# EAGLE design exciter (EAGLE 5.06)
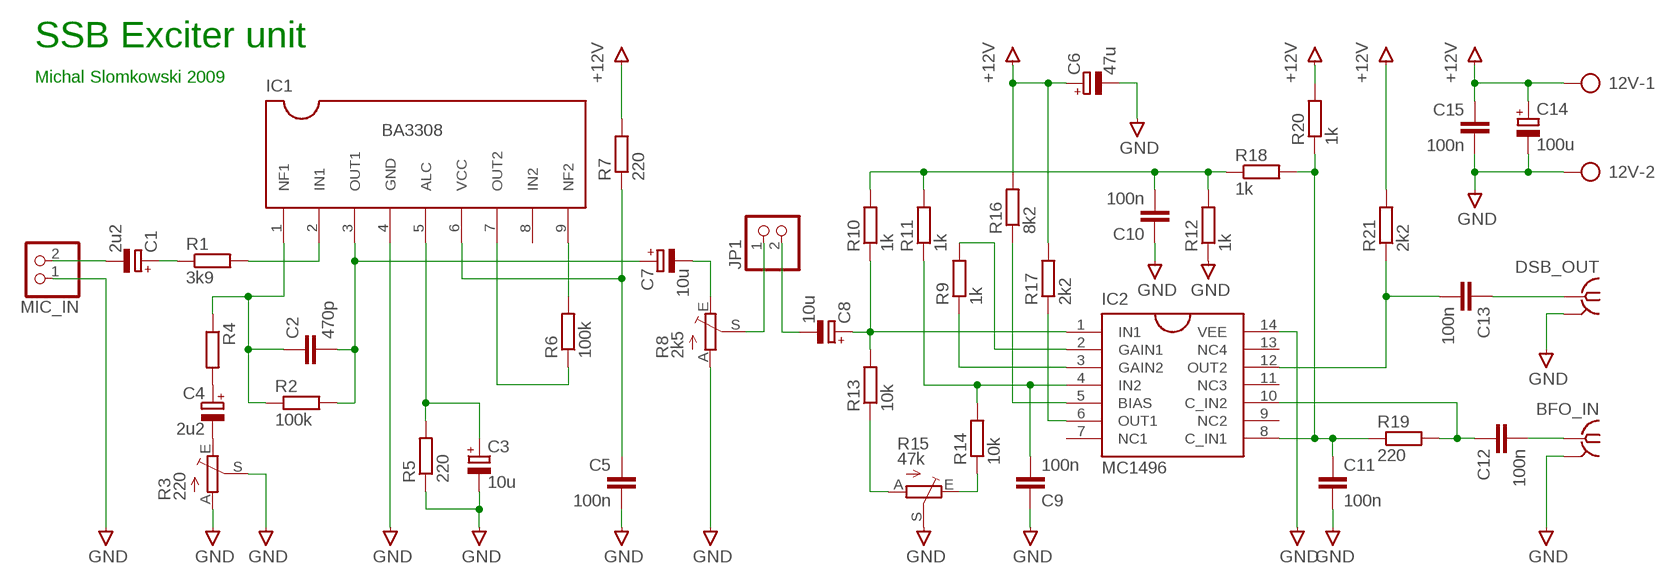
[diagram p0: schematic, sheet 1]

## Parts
12V  AK500/2  [AK500/2]
BFO_IN  BU-SMB-V  [BU-SMB-V]
C1  2u2  CPOL-EUE2.5-7  [E2,5-7]
C2  470p  C-EUC1206  [C1206]
C3  10u  CPOL-EUE2.5-7  [E2,5-7]
C4  2u2  CPOL-EUE2.5-7  [E2,5-7]
C5  100n  C-EUC1206  [C1206]
C6  47u  CPOL-EUE2.5-7  [E2,5-7]
C7  10u  CPOL-EUE2.5-7  [E2,5-7]
C8  10u  CPOL-EUE2.5-7  [E2,5-7]
C9  100n  C-EUC1206  [C1206]
C10  100n  C-EUC1206  [C1206]
C11  100n  C-EUC1206  [C1206]
C12  100n  C-EUC1206  [C1206]
C13  100n  C-EUC1206  [C1206]
C14  100u  CPOL-EUE2.5-7  [E2,5-7]
C15  100n  C-EUC1206  [C1206]
DSB_OUT  BU-SMB-V  [BU-SMB-V]
IC1  BA3308  [SIP9]
IC2  MC1496  [DIL14]
JP1  PINHD-1X2  [1X02]
MIC_IN  PINHD-1X2  [1X02]
R1  3k9  R-EU_R1206  [R1206]
R2  100k  R-EU_R1206  [R1206]
R3  220  TRIM_EU-ECP10S  [ECP10S]
R4  R-EU_R1206  [R1206]
R5  220  R-EU_R1206  [R1206]
R6  100k  R-EU_R1206  [R1206]
R7  220  R-EU_R1206  [R1206]
R8  2k5  TRIM_EU-ECP10S  [ECP10S]
R9  1k  R-EU_R1206  [R1206]
R10  1k  R-EU_R1206  [R1206]
R11  1k  R-EU_R1206  [R1206]
R12  1k  R-EU_R1206  [R1206]
R13  10k  R-EU_R1206  [R1206]
R14  10k  R-EU_R1206  [R1206]
R15  47k  TRIM_EU-S64W  [S64W]
R16  8k2  R-EU_R1206  [R1206]
R17  2k2  R-EU_R1206  [R1206]
R18  1k  R-EU_R1206  [R1206]
R19  220  R-EU_R1206  [R1206]
R20  1k  R-EU_R1206  [R1206]
R21  2k2  R-EU_R1206  [R1206]

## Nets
GND: 12V.2 BFO_IN.2(GND) C3.- C5.2 C6.- C9.1 C10.1 C11.2 C14.- C15.2 DSB_OUT.2(GND) IC1.4(GND) IC2.14(VEE) MIC_IN.1 R3.A R3.S R5.1 R8.A R12.1 R15.S
N$1: C1.- MIC_IN.2
N$2: C1.+ R1.1
N$3: IC1.2(IN1) R1.2
N$4: C2.2 C7.+ IC1.3(OUT1) R2.2
N$5: C3.+ IC1.5(ALC) R5.2
N$6: C2.1 IC1.1(NF1) R2.1 R4.1
N$7: C4.+ R4.2
N$8: C4.- R3.E
N$9: IC1.9(NF2) R6.2
N$10: IC1.7(OUT2) R6.1
N$11: C5.1 IC1.6(VCC) R7.1
N$12: C7.- R8.E
N$13: C8.- JP1.2
N$15: IC2.3(GAIN2) R9.1
N$16: IC2.2(GAIN1) R9.2
N$17: C9.2 IC2.4(IN2) R11.1 R14.2
N$18: C10.2 R10.2 R11.2 R12.2 R18.1
N$19: R14.1 R15.E
N$20: R13.1 R15.A
N$21: IC2.5(BIAS) R16.1
N$22: IC2.6(OUT1) R17.1
N$23: C12.1 IC2.10(C_IN2) R19.2
N$25: BFO_IN.1 C12.2
N$26: C13.2 IC2.12(OUT2) R21.1
N$27: C13.1 DSB_OUT.1
N$28: JP1.1 R8.S
N$38: C11.1 IC2.8(C_IN1) R18.2 R19.1 R20.1
N$54: C8.+ IC2.1(IN1) R10.1 R13.2
N$78: 12V.1 C6.+ C14.+ C15.1 R7.2 R16.2 R17.2 R20.2 R21.2 ; supply symbol labelled +12V
Unconnected: IC1.8(IN2) IC2.7(NC1) IC2.9(NC2) IC2.11(NC3) IC2.13(NC4)

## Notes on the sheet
- SSB Exciter unit
- Michal Slomkowski 2009

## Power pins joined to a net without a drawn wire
GND: BFO_IN.3(GND) BFO_IN.4(GND) BFO_IN.5(GND) DSB_OUT.3(GND) DSB_OUT.4(GND) DSB_OUT.5(GND)

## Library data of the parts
12V = con-ptr500:AK500/2: CONNECTOR
BFO_IN DSB_OUT = con-coax:BU-SMB-V: FEMALE SMB CONNECTOR Radiall distributor RS 112-2993
C1 C3 C4 C6-C8 C14 = rcl:CPOL-EU: POLARIZED CAPACITOR, European symbol
C2 C5 C9-C13 C15 = rcl:C-EU: CAPACITOR, European symbol
IC1 = receiver:BA3308
IC2 = receiver:MC1496
JP1 MIC_IN = pinhead:PINHD-1X2: PIN HEADER
R1 R2 R4-R7 R9-R14 R16-R21 = rcl:R-EU_: RESISTOR, European symbol
R3 R8 R15 = pot:TRIM_EU-: POTENTIOMETER

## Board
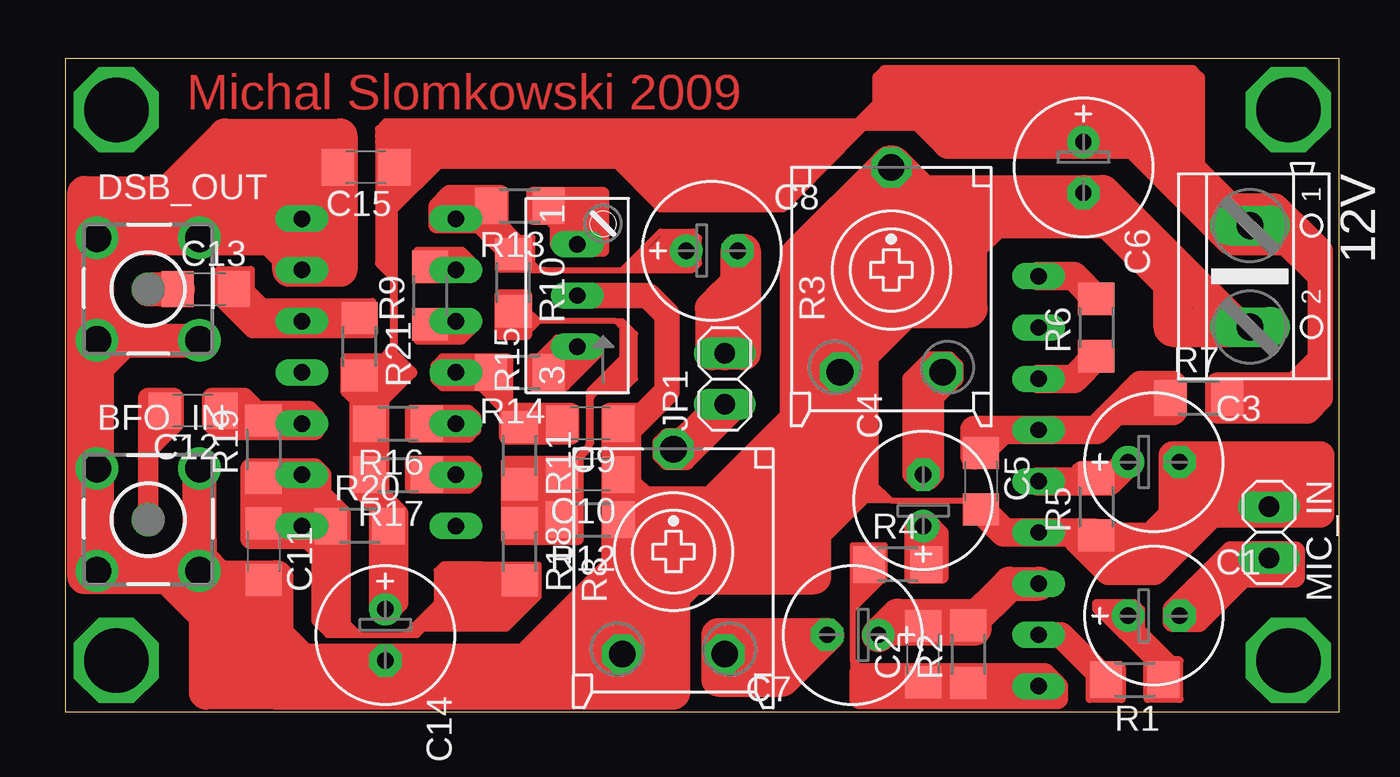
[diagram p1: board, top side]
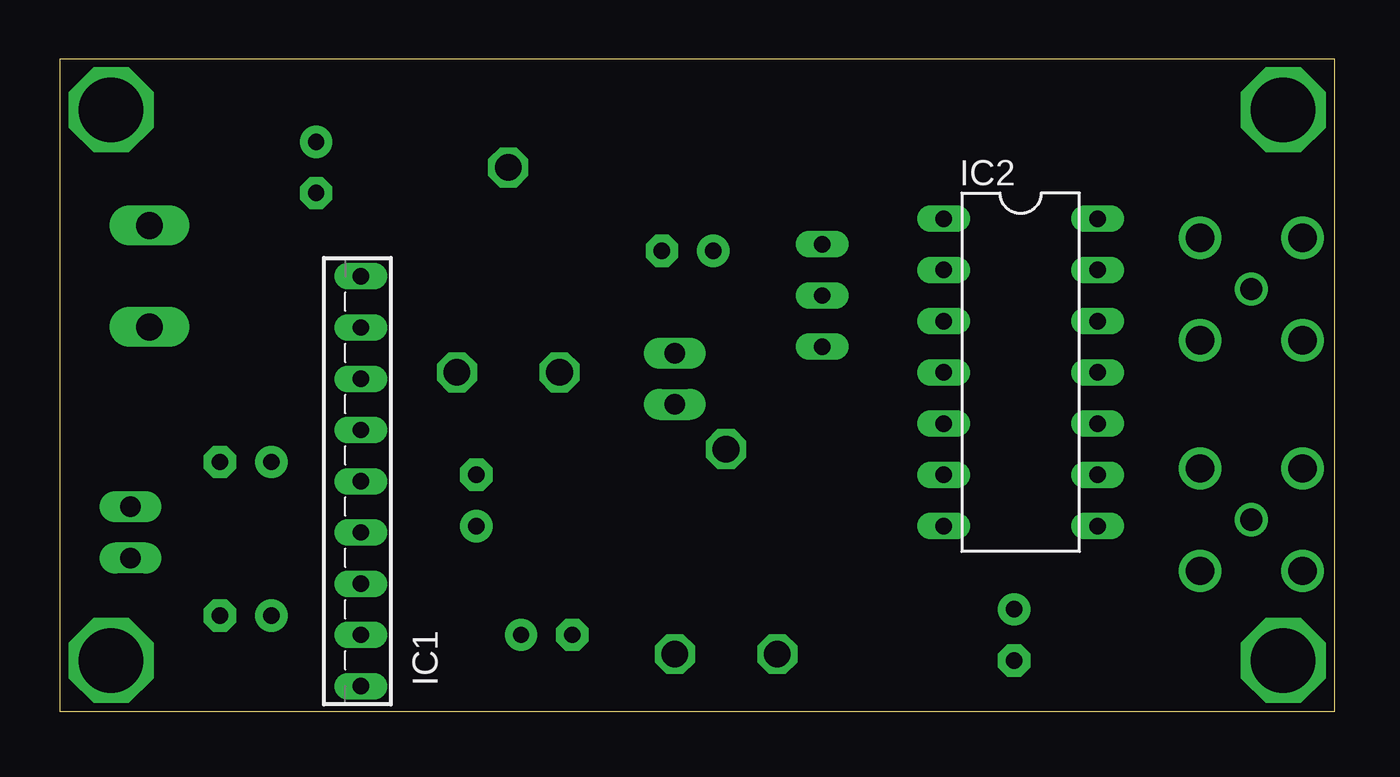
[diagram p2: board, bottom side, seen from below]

Size 63.17 x 32.38 mm. Coordinates in mm from the lower left corner, seen from the top.
Outline: 0,0 63.17,0 63.17,32.38 0,32.38 0,0
Copper layers (1*16): Top 0.035mm / dielectric 1.5mm / Bottom 0.035mm
Design rules "default": minimum track width 10mil, minimum drill 24mil, track to track 8mil, track to pad 8mil, pad to pad 8mil, via to via 8mil, smd to smd 8mil, copper to edge 40mil, drill to drill 8mil, minimum pad ring 10mil, minimum via ring 8mil, stop-mask expansion 4mil, vias tented up to drill 0mil, thermal gap 10mil

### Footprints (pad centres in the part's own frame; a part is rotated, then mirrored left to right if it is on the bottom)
AK500/2 = drill 1.321 long: 1 -2.515,0; 2 2.515,0
BU-SMB-V = drill 1.1 round: 1 0,0 | drill 1.4 round: 2 -2.54,2.54; 3 2.54,2.54; 4 2.54,-2.54; 5 -2.54,-2.54
E2,5-7 = drill 0.813 pad 1.6 round: + -1.27,0 | drill 0.813 pad 1.6 octagon: - 1.27,0
C1206 = smd 1.6 x 1.8: 1 -1.4,0; 2 1.4,0
SIP9 = drill 0.8 pad 1.27 long: 1 -13.97,0; 2 -11.43,0; 3 -8.89,0; 4 -6.35,0; 5 -3.81,0; 6 -1.27,0; 7 1.27,0; 8 3.81,0; 9 6.35,0
DIL14 = drill 0.813 long: 1 -7.62,-3.81; 2 -5.08,-3.81; 3 -2.54,-3.81; 4 0,-3.81; 5 2.54,-3.81; 6 5.08,-3.81; 7 7.62,-3.81; 8 7.62,3.81; 9 5.08,3.81; 10 2.54,3.81; 11 0,3.81; 12 -2.54,3.81; 13 -5.08,3.81; 14 -7.62,3.81
1X02 = drill 1.016 long: 1 -1.27,0; 2 1.27,0
R1206 = smd 1.6 x 1.803: 1 -1.422,0; 2 1.422,0
ECP10S = drill 1.321 octagon: A -2.54,-5.08; E 2.54,-5.08; S 0,5.08
S64W = drill 0.813 long: A 2.54,1.27; E -2.54,1.27; S 0,1.27

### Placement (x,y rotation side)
12V  58.74,21.59 270 top
BFO_IN  4.13,9.53 0 top
C1  53.98,4.76 0 top
C2  42.55,2.86 90 top
C3  53.98,12.38 0 top
C4  42.55,10.48 90 top
C5  45.4,11.43 270 top
C6  50.48,26.99 270 top
C7  39.05,3.81 180 top
C8  32.07,22.86 0 top
C9  26.04,14.29 180 top
C10  26.04,11.75 180 top
C11  9.84,7.94 270 top
C12  6.35,14.92 180 top
C13  6.99,20.95 0 top
C14  15.88,3.81 270 top
C15  14.92,26.99 180 top
DSB_OUT  4.13,20.95 0 top
IC1  48.26,15.24 90 bottom
IC2  15.56,16.83 270 bottom
JP1  32.7,16.51 90 top
MIC_IN  59.69,8.89 270 top
R1  53.02,1.59 180 top
R2  44.77,2.86 90 top
R3  40.96,21.91 0 top
R4  41.27,7.3 0 top
R5  51.12,10.16 90 top
R6  51.12,19.05 90 top
R7  56.2,15.56 0 top
R8  30.16,7.94 0 top
R9  18.1,20.64 90 top
R10  22.23,21.27 270 top
R11  22.54,12.7 270 top
R12  26.04,9.53 180 top
R13  22.54,25.08 180 top
R14  22.54,16.83 180 top
R15  26.67,20.64 90 top
R16  16.51,14.29 180 top
R17  16.51,11.75 180 top
R18  22.54,7.94 270 top
R19  9.84,13.02 90 top
R20  14.61,9.21 0 top
R21  14.61,18.1 270 top

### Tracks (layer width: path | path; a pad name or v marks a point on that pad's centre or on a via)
GND
  Top 0.305: C5.2 45.4,10.16 45.09,10.48 40.96,10.48 | 39.37,11.11 40.96,10.48 | 40.96,10.48 40.01,11.43 | 40.96,10.48 39.05,10.48
  Top 0.406: 27.46,10.79 27.43,10.82 C10.1 27.43,11.88
  Top 1.27: C9.1 27.94,13.97 29.84,15.88 29.84,19.68 28.89,20.64 R15.S | 55.24,10.16 MIC_IN.1 | 55.24,10.16 C3.- | R5.1 53.82,8.74 55.24,10.16 | 3.81,23.81 3.49,23.81 1.59,21.91 | 1.59,20.32 1.59,20 3.17,18.41 1.27,16.51 | 1.59,8.89 1.59,8.57 3.17,6.99 | 4.45,6.99 5.08,6.99 6.67,8.57
  Top 1.422: R12.1 27.46,10.48 | 27.46,10.48 27.46,10.79 27.46,11.6 | 27.43,11.88 C9.1 | R5.1 50.97,8.89 IC1.4 46.54,8.89 C5.2 | 35.24,13.65 32.07,10.48 27.46,10.48 | 39.37,11.11 38.42,10.48 35.24,13.65 | DSB_OUT.3 7.62,24.45 IC2.14 12.7,24.45 13.34,25.08 13.34,26.8 C15.2 | 35.24,13.65 R3.A
  Top 1.676: BFO_IN.4 6.67,8.57 | BFO_IN.4 7.12,6.54 C11.2 9.84,4.45 11.75,2.54 C14.- 27.3,2.54 | BFO_IN.4 4.45,6.99 3.17,6.99 BFO_IN.5 1.59,8.89 BFO_IN.2 DSB_OUT.5 | R12.1 27.46,2.69 27.3,2.54 | 27.3,2.54 R8.A | DSB_OUT.5 3.17,18.41 DSB_OUT.4 | DSB_OUT.5 1.59,20.32 1.59,21.91 DSB_OUT.2 DSB_OUT.3 13.02,23.5 | 6.67,8.57 BFO_IN.3 | 6.67,8.57 6.67,7.62 7.62,6.67 10.48,6.67 10.48,0.95 10.79,0.95 | 10.79,0.95 11.43,0.95 | 11.43,0.95 30.16,0.95 30.16,5.71 | 30.16,5.71 30.16,6.35 29.84,6.67 | 11.43,0.95 11.43,1.59 10.79,0.95 | 10.79,0.95 6.99,0.95 6.99,4.76 5.08,6.67 0.95,6.67 0.95,25.72 5.08,25.72 7.94,28.57 13.65,28.57 13.65,21.91 11.11,21.91 11.11,22.54 9.84,23.81 | 30.16,5.71 31.11,6.67 37.15,6.67 37.15,8.89 39.37,11.11
  Top 1.778: 12V.2 58.71,19.05 58.1,19.05 51.44,25.72 C6.- 42.23,25.72 41.75,26.19 | 41.75,26.19 R3.S | R3.A 38.42,22.86 41.75,26.19
  Top 2.184: 42.55,25.4 R3.S 36.51,22.54 36.51,11.11
N$1
  Top 1.422: MIC_IN.2 58.1,7.62 C1.-
N$2
  Top 1.27: C1.+ 52.7,4.13 54.61,2.22 54.61,1.75 R1.1
N$3
  Top 1.27: IC1.2 49.38,3.81 R1.2
N$4
  Top 1.676: IC1.3 46.84,6.35 R2.2 42.57,4.28 C2.2 40.77,4.26 40.64,4.13 | C7.+ 40.64,4.13 | 40.64,4.13 41.27,4.76 45.09,4.76 45.09,4.13 40.64,4.13
N$5
  Top 1.422: IC1.5 49.85,11.43 | 49.85,11.43 50.97,11.43 R5.2 51.9,11.58 52.07,11.75 | 52.07,11.75 C3.+ | 49.85,11.43 51.75,11.43 52.07,11.75
N$6
  Top 0.254: 39.05,5.08 39.05,5.4 39.69,6.03
  Top 0.305: C2.1 40.13,1.46 39.05,1.91 39.05,2.54 | 39.05,2.54 39.05,5.08 | 39.05,5.08 39.05,6.03 | 39.05,6.03 39.05,6.5 R4.1 | 39.37,2.22 39.05,2.54 | 39.05,6.03 39.05,8.26 40.64,8.26 40.64,6.67 39.05,5.08
  Top 0.61: 40.32,6.67 39.69,6.03 39.37,5.71 39.37,6.67
  Top 1.676: IC1.1 44.93,1.27 R2.1 42.57,1.44 C2.1
N$7
  Top 1.422: C4.+ 42.55,7.46 R4.2
N$8
  Top 1.422: C4.- 42.55,15.88 R3.E
N$9
  Top 1.422: IC1.9 50,21.59 R6.2
N$10
  Top 1.422: IC1.7 50,16.51 R6.1
N$11
  Top 1.27: IC1.6 46.54,13.97 C5.1
  Top 1.422: IC1.6 49.21,13.97 | 49.21,13.97 51.12,13.97 52.07,14.92 | 52.07,14.92 52.7,15.56 R7.1 | 52.07,14.92 53.34,16.19 54.93,16.19 54.93,14.92 52.39,14.92 | 49.21,13.97 45.09,13.97 45.09,12.7
N$12
  Top 1.676: R8.E 36.83,2.86 C7.- | C7.- 32.38,3.81 32.38,1.59 35.56,1.59 C7.-
N$13
  Top 1.676: 33.34,21.27 33.34,20.64 32.7,19.68 JP1.2 | 33.34,21.27 C8.- 33.66,22.86 33.66,17.78 32.07,17.78 32.07,20 32.7,20.64 | 32.7,20.64 33.02,20.95 | 33.34,21.27 32.7,20.64
N$14
  Top 0.61: 21.91,12.38 25.4,12.38 25.4,8.57 21.91,8.57 21.91,12.38
N$15
  Top 1.27: IC2.3 18.25,19.37 R9.1
N$16
  Top 1.27: IC2.2 18.25,21.91 R9.2
N$17
  Top 0.61: R14.2 21.12,16.18 23.18,14.12
  Top 1.27: IC2.4 R14.2 | R11.1 23.18,14.12 24.47,14.12 C9.2
N$18
  Top 0.305: R10.2 23.01,19.85 22.86,19.37 | 27.3,19.37 23.5,19.37 | 27.3,19.37 27.62,19.37 28.26,18.73 | 23.5,19.37 23.18,19.37 | 23.5,19.37 22.86,20 | 23.5,19.37 22.86,18.73 | 28.26,18.73 27.94,18.73 27.62,19.05 | 28.26,18.73 28.26,16.51 27.62,15.88 26.35,15.88 26.04,15.56 | 27.62,19.05 27.3,19.37 | 27.62,19.05 27.62,16.19
  Top 0.406: 24.3,11.28 24.64,11.62 C10.2 25.91,13.02 26.04,13.34 26.04,15.56 26.04,15.88 27.94,17.78 27.94,18.73
  Top 0.61: 22.86,19.37 22.86,18.73 21.59,18.73 21.59,20.64 22.86,20.64 22.86,20 22.86,19.37 | 21.91,19.05 22.86,19.05 23.18,19.37 22.86,19.37 | 27.94,17.78 27.94,17.46 27.94,16.51 | 27.62,16.19 26.67,16.19
  Top 0.813: 27.94,17.46 26.99,16.51
  Top 1.27: R18.1 R11.2 24.3,11.28 24.61,10.96 R12.2
N$19
  Top 1.27: R15.E 25.23,18.1 R14.1
N$20
  Top 1.27: R15.A 25.4,23.65 R13.1
N$21
  Top 1.27: R16.1 IC2.5
N$22
  Top 1.27: R17.1 IC2.6
N$23
  Top 1.27: IC2.10 9.99,14.29 R19.2 9.68,14.61 C12.1
N$24
  Top 0.61: 21.91,14.92 20.64,16.19 18.73,16.19 18.41,16.51 18.41,17.14 18.73,17.46 21.91,17.46 21.91,15.24
  Top 0.813: 21.91,13.65 25.08,13.65 25.08,14.92 21.91,14.92 21.91,13.65
N$25
  Top 1.016: BFO_IN.1 4.13,13.02 | 4.13,13.02 4.13,13.34 | 4.13,13.34 4.13,14.1 C12.2 | 4.13,13.34 4.13,15.56 5.4,15.56 5.4,14.29 4.13,13.02
N$26
  Top 1.016: IC2.12 14.45,19.37 R21.1
  Top 1.27: IC2.12 9.97,19.37 C13.2
N$27
  Top 1.676: DSB_OUT.1 C13.1
N$28
  Top 1.422: R8.S JP1.1
N$29  (via drill 3.2)
  other vias: 2.54,2.54
N$30  (via drill 3.2)
  other vias: 2.54,29.84
N$31  (via drill 3.2)
  other vias: 60.64,2.54
N$32
  Top 0.61: 21.59,24.13 22.54,23.18
  Top 0.813: 21.59,24.13 21.59,25.72 19.05,25.72 18.41,25.08 18.41,24.13 20.95,24.13
N$33  (via drill 3.2)
  other vias: 60.64,29.84
N$34
  Top 0.406: 15.24,19.05 15.24,18.73 9.21,18.73 7.62,20.32 7.62,21.91 9.21,21.91 9.21,20.95 | 15.24,20.32 9.84,20.32 9.21,20.95 | 9.21,20.95 8.89,21.27
N$35
  Top 0.813: 9.53,19.05 7.94,20.64
N$36
  Top 0.813: 9.84,20 13.97,20
N$37
  Top 1.016: 7.3,15.56 8.89,15.56 9.53,14.92 12.06,14.92 12.38,14.61 12.38,13.97 7.62,13.97 7.3,14.29 7.3,15.56
N$38
  Top 0.305: R20.1 13.18,4.6 13.97,3.81 14.29,3.81 | 14.29,3.81 14.61,3.81 | 14.61,3.81 16.83,3.81 | 18.1,5.08 19.68,5.4 21.91,4.13 | 18.1,5.08 19.05,4.76 | 14.29,3.81 13.02,3.81 12.38,4.45 12.38,8.26 | 14.61,3.81 13.97,4.45 | 14.29,3.81 13.65,4.45 | 21.91,4.13 23.5,5.71 23.5,7.3 20.64,7.3 | 20.64,7.3 20.32,7.3 20,6.99 18.73,5.71 18.1,5.08 | 16.83,3.81 18.1,5.08 | 17.78,4.13 21.91,4.13 | 17.78,4.13 17.46,4.13 17.14,3.81 16.83,3.81 | 16.83,3.81 17.46,3.81 17.78,4.13 | 20.64,7.3 18.73,7.3 18.41,6.99 18.41,4.76
  Top 0.61: IC2.8 11.75,8.57 12.7,7.62
  Top 0.813: 19.05,4.76 19.68,5.4 20.47,4.45 R18.2 | 20,6.99 19.05,6.99 18.73,6.67 18.73,5.71 18.73,6.03 19.37,6.67
  Top 1.016: 13.02,8.57 9.21,8.57 9.21,12.06 12.38,12.06 12.7,11.75 12.7,10.79 13.65,9.84 13.65,8.89 | 13.02,8.57 13.65,8.57 13.65,8.89 | 13.65,8.89 13.65,8.26 | 13.65,8.89 13.65,4.45 13.02,4.45 13.02,8.57 | 20.32,6.67 18.41,4.76 19.37,4.76
  Top 1.27: R19.1 C11.1 11.62,9.34 IC2.8 R20.1 | 19.37,4.76 20.32,4.76 21.27,6.67
N$39
  Top 1.676: 1.59,24.77 6.67,24.77 8.26,26.35
N$40
  Top 1.676: 6.35,25.72 8.26,27.62
N$41
  Top 0.61: 17.14,14.92 20,14.92 20.32,14.61 20.32,13.97 20,13.65 17.14,13.65 17.14,14.92
N$42
  Top 0.61: 17.14,12.38 20,12.38 20.32,12.06 20.32,11.43 20,11.11 17.14,11.11 17.14,12.38
N$43
  Top 0.406: 20.32,22.23 19.68,22.86 17.46,22.86
N$44
  Top 0.406: 18.41,22.54 19.68,22.54
N$45
  Top 0.406: 20,18.73 20.32,19.05 | 20,18.73 19.68,18.41 17.46,18.41 | 20,18.73 19.05,18.73
N$46
  Top 0.61: 26.35,17.78 24.77,16.19 23.81,16.19 | 23.81,16.19 24.13,16.19 | 23.81,16.19 23.18,16.19 23.18,17.46 23.5,17.46 24.45,18.41 26.04,18.41
N$47
  Top 0.61: 24.45,16.51 26.04,18.1
N$48
  Top 0.813: 18.73,25.08 20.64,25.08
N$49
  Top 0.813: 24.45,23.18 24.45,24.13 24.13,24.45
N$50
  Top 0.61: 23.81,24.45 23.18,24.45 23.18,25.72 26.67,25.72 26.67,22.86 25.72,22.86
N$51
  Top 1.016: 24.45,25.08 26.04,25.08 26.04,23.5
N$52
  Top 1.016: 25.4,24.45 25.72,24.45
N$53
  Top 0.61: 31.11,22.23 31.11,23.5
N$54
  Top 0.305: C8.+ 29.53,22.86 28.89,22.86 27.94,21.91 27.62,21.91 | 23.18,21.91 23.01,21.91 R10.1 | 23.18,21.91 23.81,21.91 | 23.81,21.91 27.62,21.91 | 23.18,21.91 21.59,21.91 21.59,22.23 | 23.18,21.91 23.18,22.23 | 23.18,22.23 23.18,23.5 22.54,23.5 21.59,24.45 | 23.81,21.91 23.5,21.91 23.18,22.23 | 27.62,21.91 31.11,21.91 31.43,22.23 31.43,23.5 31.11,23.81 29.53,23.81 27.62,21.91
  Top 0.61: 29.84,23.5 28.57,22.23 29.53,22.23 29.53,22.86
  Top 1.016: R10.1 22.07,22.7 20.32,24.45
  Top 1.27: IC2.1 20.32,24.45 21.27,24.45 21.27,24.93 R13.2
N$55
  Top 1.016: 22.86,5.71 21.91,4.76 20.64,4.76
N$56
  Top 1.016: 44.13,1.91 43.81,1.91 | 44.13,1.91 48.58,1.91 49.21,1.27 49.21,0.64 39.37,0.64 39.37,1.91 44.13,1.91
N$57
  Top 0.254: 15.56,17.46 16.19,18.1
  Top 0.61: 13.97,17.46 13.97,17.14 | 13.97,17.46 15.56,17.46 15.88,17.46 | 15.88,17.46 16.51,17.46 | 16.51,17.46 17.14,16.83 15.56,15.24 | 13.97,17.46 13.97,15.88 14.61,15.24 | 16.51,17.46 16.19,17.78 15.88,17.46
  Top 1.016: 16.19,5.08 16.51,5.4 16.51,9.84 15.56,10.79 15.56,15.24 15.56,16.83 | 15.56,5.08 15.56,10.16 14.61,11.11 14.61,15.24 14.61,16.19
N$58
  Top 0.61: 16.19,17.14 16.19,16.19
N$59
  Top 0.61: 16.51,16.51 16.51,16.83
N$60
  Top 0.813: 21.59,6.99 20.64,6.99
N$61
  Top 0.61: 17.78,4.45 19.05,4.76
N$62
  Top 0.813: 26.99,14.92 26.99,14.61 | 26.99,14.92 28.57,14.92 | 26.99,14.92 26.99,7.3 21.91,2.22
N$63
  Top 2.54: 27.3,5.4 26.67,5.4 24.13,2.86 27.3,2.86 27.62,3.17
N$64
  Top 0.305: 20,6.03 20,5.4
N$65
  Top 0.406: 16.19,24.77 18.73,27.3
N$66
  Top 1.422: 50.48,11.75 51.75,11.75
N$67
  Top 0.61: 16.51,27.94 15.88,27.94
N$68
  Top 0.61: 15.88,27.62 15.88,22.23 16.19,21.91
N$69
  Top 1.016: 15.88,28.57 37.15,28.57
  Top 1.676: 37.15,28.57 38.1,28.57
N$70
  Top 1.016: 38.42,28.89 39.05,28.89
N$71
  Top 1.016: 36.83,26.67 35.56,26.67 35.56,26.35 35.88,26.04
N$72
  Top 1.016: 35.56,26.04 35.56,25.4
N$73
  Top 1.016: 28.26,26.67 29.53,26.67 29.53,25.72 29.21,26.04
N$74
  Top 1.016: 39.69,1.27 41.59,1.27
N$75
  Top 0.61: 42.23,9.53 41.91,9.21 41.91,6.67 43.5,6.67 43.5,8.89 42.86,9.53
N$76
  Top 1.422: 54.93,10.16 54.93,12.7 62.23,12.7 62.23,9.84 56.83,9.84 53.98,6.99 51.75,6.99 50.16,8.57
N$77
  Top 0.813: 42.86,11.43 43.18,11.75 43.18,15.56 | 42.23,11.43 41.91,11.75 41.91,16.51 42.86,17.46 43.81,17.46 44.13,17.14 44.13,16.51 43.18,15.56 | 43.18,15.56 42.86,15.24
N$78
  Top 0.406: 16.19,21.59 15.56,22.23 15.56,28.26 | 15.56,28.26 17.46,28.26 | 15.56,28.26 15.56,28.89 15.88,29.21 39.69,29.21 | R21.2 14.76,16.83 15.24,16.83 15.56,17.14 | 15.56,17.14 16.32,17.59 C15.1 | C14.+ 15.88,5.88 16.03,6.03 | 15.56,17.14 15.56,17.46
  Top 0.61: 37.47,27.62 38.1,27.62 38.42,27.94 | 38.42,27.94 39.69,29.21 40.32,29.84 | 40.32,29.84 40.64,30.16 41.91,30.16 42.23,29.84 | 38.42,27.94 35.56,25.08 29.53,25.08 27.3,27.3 | 40.32,29.84 40.32,31.43 40.64,31.75 55.88,31.75 56.2,31.43 56.2,25.72
  Top 0.813: 39.69,29.21 42.86,29.21 | 40.32,29.84 41.91,29.84
  Top 1.27: R20.2 16.03,10.01 14.92,11.11 14.92,11.58 R17.2 | R7.2 61.28,15.56 62.23,16.51 | 62.23,21.27 62.23,22.86 61.59,23.5 | 62.23,21.27 62.23,17.46 | 62.23,17.46 62.23,16.51 | 61.59,23.5 60.96,24.13 58.76,24.13 12V.1 | 18.1,27.62 16.19,25.72 | 62.23,17.46 60.96,16.19 57.15,16.19 57.15,14.92 61.59,14.92 62.23,15.56 62.23,16.51 | 61.59,23.5 60.01,25.08 57.78,25.08 55.56,27.3 | 62.23,21.27 62.23,21.59 60.33,23.5
  Top 1.422: R17.2 R16.2 14.92,16.04 R21.2 | 16.03,5.23 16.03,6.03 R20.2 | 37.47,27.62 18.1,27.62 16.96,27.62 C15.1
  Top 1.676: 12V.1 57.17,24.11 56.2,25.08 | 56.2,25.08 53.02,28.26 C6.+ 43.81,28.26 42.86,29.21 42.23,29.84 | 56.2,25.08 57.78,23.5 60.33,23.5 60.96,23.5
N$79
  Top 1.422: 51.44,8.26 54.61,8.26
N$80
  Top 1.016: 59.69,7.94 60.01,7.94 | 59.69,7.94 57.78,7.94 54.93,5.08 54.93,4.45 56.2,4.45 59.05,7.3 60.96,7.3 | 60.96,7.3 60.96,7.94 59.69,7.94 | 60.96,7.3 60.96,6.67 58.1,6.67
N$81
  Top 0.406: 53.34,4.13 53.34,5.08 53.02,5.4 51.12,5.4 51.12,5.08 52.39,3.81 52.7,3.81 53.98,2.54
N$82
  Top 0.406: 53.66,2.54 53.66,0.64 55.24,0.64 55.24,2.54 54.61,2.54
N$83
  Top 0.61: 51.44,5.08 52.07,5.08 52.07,4.45 51.75,4.76
N$84
  Top 0.406: 50.8,1.91 50.8,0.64 52.39,0.64 52.39,2.22
N$85
  Top 1.676: 55.56,28.26 53.98,28.26
N$86
  Top 0.61: 38.42,28.57 38.73,28.57 40.96,30.8
N$87
  Top 1.676: 43.5,31.11 41.27,31.11 | 43.5,31.11 43.81,31.11 | 43.5,29.21 43.5,31.11
N$88
  Top 1.93: 58.74,19.05 54.93,19.05 54.93,21.91
N$89
  Top 1.93: 55.24,21.27 54.93,21.27 51.12,25.08
N$90
  Top 1.93: 52.39,24.45 46.04,24.45 44.77,23.18 44.77,20 41.59,20 39.37,17.78 39.37,11.43
N$91
  Top 0.813: 31.75,14.92 30.48,13.65 29.84,13.65 29.53,13.34 29.53,12.7 29.84,12.38 30.8,12.38 33.34,14.92
N$92
  Top 1.676: 28.57,1.59 28.57,9.84
N$93
  Top 1.676: 37.78,10.79 37.78,15.56
N$94
  Top 0.61: 40.01,11.11 40.32,10.79 40.01,10.79
N$95
  Top 0.61: 28.26,13.97 28.26,11.43 28.89,10.79
N$96
  Top 1.93: 35.24,12.38 35.24,11.11 33.66,11.11
(copper drawn outside any net)
  shapes: Top area x11

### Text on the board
Top: Michal Slomkowski 2009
